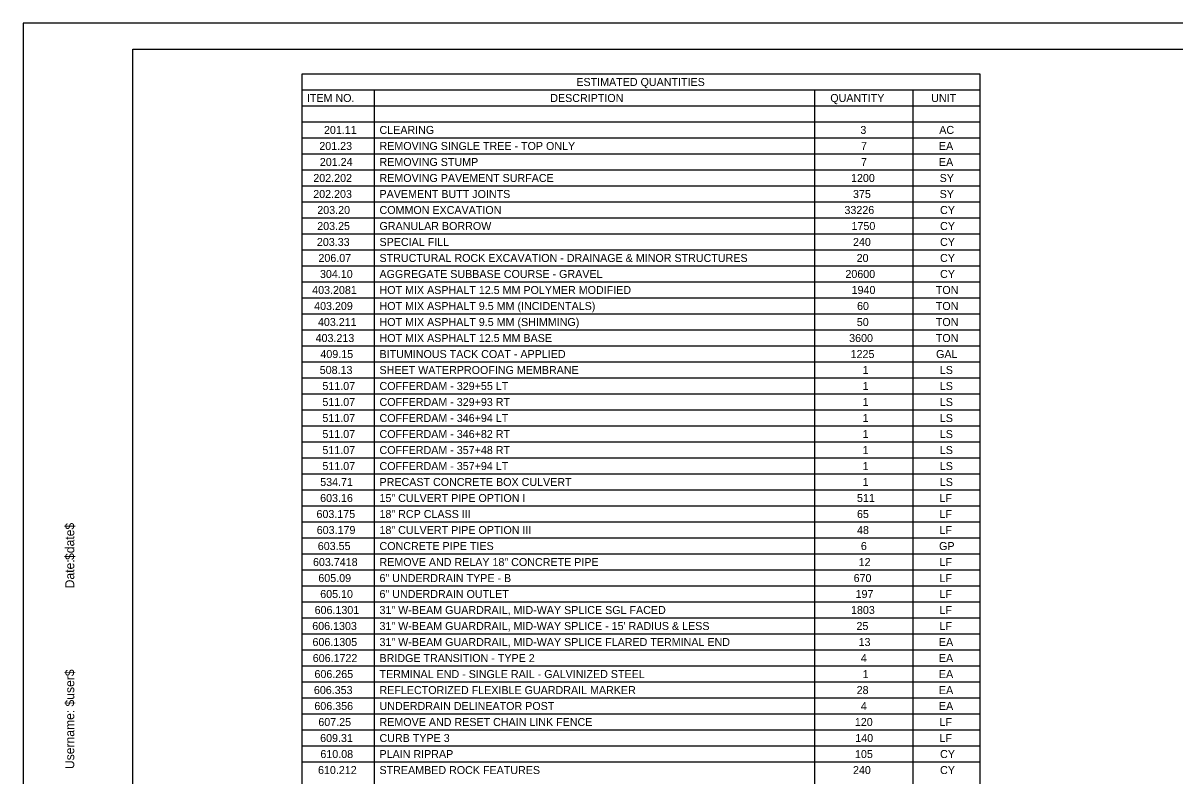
# Model space of a CAD drawing. Extents: x -0.13 to 2.7, y -0.05 to 1.78.
# Drawn here: x -0.135 to 1.282, y 0.856 to 1.782 of the extents above; entities that cross this region are included whole.
import ezdxf

# ---------------------------------------------------------------- set-up
doc = ezdxf.new("R2010")
doc.units = 0
for name, color, linetype in [('ANNOTATION', 7, 'Continuous'), ('BORDER', 7, 'Continuous'), ('Default', 7, 'Continuous'), ('PLOT BOUNDARY', 7, 'Continuous')]:
    doc.layers.add(name, color=color, linetype=linetype)

msp = doc.modelspace()

# ---------------------------------------------------------------- linework, layer by layer
at = {"layer": 'BORDER'}
for p, q in [((0.2083, 1.7003), (1.0417, 1.7003)), ((0.2969, 1.7003), (0.2969, 0.0465)), ((0.8383, 1.7003), (0.8383, 0.0465)), ((0.9596, 1.7003), (0.9596, 0.0465)), ((0.2083, 1.6806), (1.0417, 1.6806)), ((0.2083, 1.6609), (1.0417, 1.6609)), ((0.2083, 1.6413), (1.0417, 1.6413)), ((0.2083, 1.6216), (1.0417, 1.6216)), ((0.2083, 1.6019), (1.0417, 1.6019)), ((0.2083, 1.5822), (1.0417, 1.5822)), ((0.2083, 1.5625), (1.0417, 1.5625)), ((0.2083, 1.5428), (1.0417, 1.5428)), ((0.2083, 1.5231), (1.0417, 1.5231)), ((0.2083, 1.5035), (1.0417, 1.5035)), ((0.2083, 1.4838), (1.0417, 1.4838)), ((0.2083, 1.4641), (1.0417, 1.4641)), ((0.2083, 1.4444), (1.0417, 1.4444)), ((0.2083, 1.4247), (1.0417, 1.4247)), ((0.2083, 1.405), (1.0417, 1.405)), ((0.2083, 1.3853), (1.0417, 1.3853)), ((0.2083, 1.3657), (1.0417, 1.3657)), ((0.2083, 1.346), (1.0417, 1.346)), ((0.2083, 1.3263), (1.0417, 1.3263)), ((0.2083, 1.3066), (1.0417, 1.3066)), ((0.2083, 1.2869), (1.0417, 1.2869)), ((0.2083, 1.2672), (1.0417, 1.2672)), ((0.2083, 1.2475), (1.0417, 1.2475)), ((0.2083, 1.2279), (1.0417, 1.2279)), ((0.2083, 1.2082), (1.0417, 1.2082)), ((0.2083, 1.1885), (1.0417, 1.1885)), ((0.2083, 1.1688), (1.0417, 1.1688)), ((0.2083, 1.1491), (1.0417, 1.1491)), ((0.2083, 1.1294), (1.0417, 1.1294)), ((0.2083, 1.1097), (1.0417, 1.1097)), ((0.2083, 1.09), (1.0417, 1.09)), ((0.2083, 1.0704), (1.0417, 1.0704)), ((0.2083, 1.0507), (1.0417, 1.0507)), ((0.2083, 1.031), (1.0417, 1.031)), ((0.2083, 1.0113), (1.0417, 1.0113)), ((0.2083, 0.9916), (1.0417, 0.9916)), ((0.2083, 0.9719), (1.0417, 0.9719)), ((0.2083, 0.9522), (1.0417, 0.9522)), ((0.2083, 0.9326), (1.0417, 0.9326)), ((0.2083, 0.9129), (1.0417, 0.9129)), ((0.2083, 0.8932), (1.0417, 0.8932)), ((0.2083, 0.8735), (1.0417, 0.8735))]:
    msp.add_line(p, q, dxfattribs=at)
for points in [[(0, 1.75), (2.6667, 1.75), (2.6667, 0), (0, 0)], [(0.2083, 1.72), (1.0417, 1.72), (1.0417, 0.0465), (0.2083, 0.0465)]]:
    msp.add_lwpolyline(points, close=True, dxfattribs=at)
at = {"layer": 'Default'}
for p, q in [((0, 1.75), (1.25, 1.75)), ((1.25, 1.75), (2.5, 1.75))]:
    msp.add_line(p, q, dxfattribs=at)
at = {"layer": 'PLOT BOUNDARY'}
msp.add_lwpolyline([(-0.1349, -0.051), (2.6984, -0.051), (2.6984, 1.7823), (-0.1349, 1.7823)], close=True, dxfattribs=at)

# ---------------------------------------------------------------- texts
at = {"layer": 'ANNOTATION'}
for s, height, p in [('201.11', 0.00984, (0.2352, 1.6459)), ('CLEARING', 0.00984, (0.3035, 1.6459)), ('3', 0.00984, (0.8949, 1.6459)), ('AC', 0.00984, (0.9919, 1.6459)), ('201.23', 0.00984, (0.2295, 1.6262)), ('REMOVING SINGLE TREE - TOP ONLY', 0.009843, (0.3035, 1.6262)), ('7', 0.00984, (0.8957, 1.6262)), ('EA', 0.00984, (0.9915, 1.6262)), ('201.24', 0.00984, (0.2301, 1.6065)), ('REMOVING STUMP', 0.009843, (0.3035, 1.6065)), ('7', 0.00984, (0.8957, 1.6065)), ('EA', 0.00984, (0.9915, 1.6065)), ('202.202', 0.00984, (0.2221, 1.5868)), ('REMOVING PAVEMENT SURFACE', 0.009843, (0.3035, 1.5868)), ('1200', 0.00984, (0.8834, 1.5868)), ('SY', 0.00984, (0.9924, 1.5868)), ('202.203', 0.00984, (0.222, 1.5671)), ('PAVEMENT BUTT JOINTS', 0.009843, (0.3035, 1.5671)), ('375', 0.00984, (0.8858, 1.5671)), ('SY', 0.00984, (0.9924, 1.5671)), ('203.20', 0.00984, (0.227, 1.5474)), ('COMMON EXCAVATION', 0.009843, (0.3035, 1.5474)), ('33226', 0.00984, (0.8753, 1.5474)), ('CY', 0.00984, (0.9929, 1.5474)), ('203.25', 0.00984, (0.2269, 1.5277)), ('GRANULAR BORROW', 0.009843, (0.3035, 1.5277)), ('1750', 0.00984, (0.884, 1.5277)), ('CY', 0.00984, (0.9929, 1.5277)), ('203.33', 0.00984, (0.2265, 1.5081)), ('SPECIAL FILL', 0.009843, (0.3035, 1.5081)), ('240', 0.00984, (0.8858, 1.5081)), ('CY', 0.00984, (0.9929, 1.5081)), ('206.07', 0.00984, (0.2284, 1.4884)), ('STRUCTURAL ROCK EXCAVATION - DRAINAGE & MINOR STRUCTURES', 0.009843, (0.3035, 1.4884)), ('20', 0.00984, (0.8903, 1.4884)), ('CY', 0.00984, (0.9929, 1.4884)), ('304.10', 0.00984, (0.2303, 1.4687)), ('AGGREGATE SUBBASE COURSE - GRAVEL', 0.009843, (0.3035, 1.4687)), ('20600', 0.00984, (0.8765, 1.4687)), ('CY', 0.00984, (0.9929, 1.4687)), ('403.2081', 0.00984, (0.2207, 1.449)), ('HOT MIX ASPHALT 12.5 MM POLYMER MODIFIED', 0.009843, (0.3035, 1.449)), ('1940', 0.00984, (0.8841, 1.449)), ('TON', 0.00984, (0.9877, 1.449)), ('403.209', 0.00984, (0.2231, 1.4293)), ('HOT MIX ASPHALT 9.5 MM (INCIDENTALS)', 0.009843, (0.3035, 1.4293)), ('60', 0.00984, (0.8908, 1.4293)), ('TON', 0.00984, (0.9877, 1.4293)), ('403.211', 0.00984, (0.2278, 1.4096)), ('HOT MIX ASPHALT 9.5 MM (SHIMMING)', 0.009843, (0.3035, 1.4096)), ('50', 0.00984, (0.8905, 1.4096)), ('TON', 0.00984, (0.9877, 1.4096)), ('403.213', 0.00984, (0.2249, 1.3899)), ('HOT MIX ASPHALT 12.5 MM BASE', 0.009843, (0.3035, 1.3899)), ('3600', 0.00984, (0.8811, 1.3899)), ('TON', 0.00984, (0.9877, 1.3899)), ('409.15', 0.00984, (0.2308, 1.3702)), ('BITUMINOUS TACK COAT - APPLIED', 0.009843, (0.3035, 1.3702)), ('1225', 0.00984, (0.8829, 1.3702)), ('GAL', 0.00984, (0.988, 1.3702)), ('508.13', 0.00984, (0.23, 1.3506)), ('SHEET WATERPROOFING MEMBRANE', 0.009843, (0.3035, 1.3506)), ('1', 0.00984, (0.8977, 1.3506)), ('LS', 0.00984, (0.9926, 1.3506)), ('511.07', 0.00984, (0.2333, 1.3309)), ('COFFERDAM - 329+55 LT', 0.009843, (0.3035, 1.3309)), ('1', 0.00984, (0.8977, 1.3309)), ('LS', 0.00984, (0.9926, 1.3309)), ('511.07', 0.00984, (0.2333, 1.3112)), ('COFFERDAM - 329+93 RT', 0.009843, (0.3035, 1.3112)), ('1', 0.00984, (0.8977, 1.3112)), ('LS', 0.00984, (0.9926, 1.3112)), ('511.07', 0.00984, (0.2333, 1.2915)), ('COFFERDAM - 346+94 LT', 0.009843, (0.3035, 1.2915)), ('1', 0.00984, (0.8977, 1.2915)), ('LS', 0.00984, (0.9926, 1.2915)), ('511.07', 0.00984, (0.2333, 1.2718)), ('COFFERDAM - 346+82 RT', 0.009843, (0.3035, 1.2718)), ('1', 0.00984, (0.8977, 1.2718)), ('LS', 0.00984, (0.9926, 1.2718)), ('511.07', 0.00984, (0.2333, 1.2521)), ('COFFERDAM - 357+48 RT', 0.009843, (0.3035, 1.2521)), ('1', 0.00984, (0.8977, 1.2521)), ('LS', 0.00984, (0.9926, 1.2521)), ('511.07', 0.00984, (0.2333, 1.2324)), ('COFFERDAM - 357+94 LT', 0.009843, (0.3035, 1.2324)), ('1', 0.00984, (0.8977, 1.2324)), ('LS', 0.00984, (0.9926, 1.2324)), ('534.71', 0.00984, (0.2306, 1.2128)), ('PRECAST CONCRETE BOX CULVERT', 0.009843, (0.3035, 1.2128)), ('1', 0.00984, (0.8977, 1.2128)), ('LS', 0.00984, (0.9926, 1.2128)), ('603.16', 0.00984, (0.2305, 1.1931)), ('15" CULVERT PIPE OPTION I', 0.009843, (0.3035, 1.1931)), ('511', 0.00984, (0.8907, 1.1931)), ('LF', 0.00984, (0.9922, 1.1931)), ('603.175', 0.00984, (0.226, 1.1734)), ('18" RCP CLASS III', 0.009843, (0.3035, 1.1734)), ('65', 0.00984, (0.8907, 1.1734)), ('LF', 0.00984, (0.9922, 1.1734)), ('603.179', 0.00984, (0.2263, 1.1537)), ('18" CULVERT PIPE OPTION III', 0.009843, (0.3035, 1.1537)), ('48', 0.00984, (0.8908, 1.1537)), ('LF', 0.00984, (0.9922, 1.1537)), ('603.55', 0.00984, (0.2276, 1.134)), ('CONCRETE PIPE TIES', 0.009843, (0.3035, 1.134)), ('6', 0.00984, (0.8955, 1.134)), ('GP', 0.00984, (0.9917, 1.134)), ('603.7418', 0.00984, (0.2217, 1.1143)), ('REMOVE AND RELAY 18" CONCRETE PIPE', 0.009843, (0.3035, 1.1143)), ('12', 0.00984, (0.8928, 1.1143)), ('LF', 0.00984, (0.9922, 1.1143)), ('605.09', 0.00984, (0.2283, 1.0946)), ('6" UNDERDRAIN TYPE - B', 0.009843, (0.3035, 1.0946)), ('670', 0.00984, (0.8866, 1.0946)), ('LF', 0.00984, (0.9922, 1.0946)), ('605.10', 0.00984, (0.2306, 1.075)), ('6" UNDERDRAIN OUTLET', 0.009843, (0.3035, 1.075)), ('197', 0.00984, (0.889, 1.075)), ('LF', 0.00984, (0.9922, 1.075)), ('606.1301', 0.00984, (0.2237, 1.0553)), ('31" W-BEAM GUARDRAIL, MID-WAY SPLICE SGL FACED', 0.009843, (0.3035, 1.0553)), ('1803', 0.00984, (0.8834, 1.0553)), ('LF', 0.00984, (0.9922, 1.0553)), ('606.1303', 0.00984, (0.2208, 1.0356)), ('31" W-BEAM GUARDRAIL, MID-WAY SPLICE - 15\' RADIUS & LESS', 0.009843, (0.3035, 1.0356)), ('25', 0.00984, (0.8901, 1.0356)), ('LF', 0.00984, (0.9922, 1.0356)), ('606.1305', 0.00984, (0.2211, 1.0159)), ('31" W-BEAM GUARDRAIL, MID-WAY SPLICE FLARED TERMINAL END', 0.009843, (0.3035, 1.0159)), ('13', 0.00984, (0.8927, 1.0159)), ('EA', 0.00984, (0.9915, 1.0159)), ('606.1722', 0.00984, (0.2214, 0.9962)), ('BRIDGE TRANSITION - TYPE 2', 0.009843, (0.3035, 0.9962)), ('4', 0.00984, (0.8955, 0.9962)), ('EA', 0.00984, (0.9915, 0.9962)), ('606.265', 0.00984, (0.2235, 0.9765)), ('TERMINAL END - SINGLE RAIL - GALVINIZED STEEL', 0.009843, (0.3035, 0.9765)), ('1', 0.00984, (0.8977, 0.9765)), ('EA', 0.00984, (0.9915, 0.9765)), ('606.353', 0.00984, (0.2228, 0.9568)), ('REFLECTORIZED FLEXIBLE GUARDRAIL MARKER', 0.009843, (0.3035, 0.9568)), ('28', 0.00984, (0.8903, 0.9568)), ('EA', 0.00984, (0.9915, 0.9568)), ('606.356', 0.00984, (0.2234, 0.9372)), ('UNDERDRAIN DELINEATOR POST', 0.009843, (0.3035, 0.9372)), ('4', 0.00984, (0.8955, 0.9372)), ('EA', 0.00984, (0.9915, 0.9372)), ('607.25', 0.00984, (0.2283, 0.9175)), ('REMOVE AND RESET CHAIN LINK FENCE', 0.009843, (0.3035, 0.9175)), ('120', 0.00984, (0.8881, 0.9175)), ('LF', 0.00984, (0.9922, 0.9175)), ('609.31', 0.00984, (0.2305, 0.8978)), ('CURB TYPE 3', 0.009843, (0.3035, 0.8978)), ('140', 0.00984, (0.8886, 0.8978)), ('LF', 0.00984, (0.9922, 0.8978)), ('610.08', 0.00984, (0.2308, 0.8781)), ('PLAIN RIPRAP', 0.009843, (0.3035, 0.8781)), ('105', 0.00984, (0.8883, 0.8781)), ('CY', 0.00984, (0.9929, 0.8781)), ('610.212', 0.00984, (0.2279, 0.8584)), ('STREAMBED ROCK FEATURES', 0.009843, (0.3035, 0.8584)), ('240', 0.00984, (0.8858, 0.8584)), ('CY', 0.00984, (0.9929, 0.8584))]:
    msp.add_text(s, height=height, dxfattribs=at).set_placement(p)
at = {"layer": 'BORDER'}
for s, height, p in [('ESTIMATED QUANTITIES', 0.009843, (0.5456, 1.7049)), ('ITEM NO.', 0.00984, (0.2142, 1.6852)), ('DESCRIPTION', 0.009843, (0.5135, 1.6852)), ('QUANTITY', 0.00984, (0.8579, 1.6852)), ('UNIT', 0.00984, (0.982, 1.6852))]:
    msp.add_text(s, height=height, dxfattribs=at).set_placement(p)
for s, p in [('$date$', (-0.0719, 1.1218)), ('Date:', (-0.0719, 1.0869)), ('$user$', (-0.0719, 0.9415)), ('Username:', (-0.0719, 0.8645))]:
    msp.add_text(s, height=0.01116, rotation=90, dxfattribs=at).set_placement(p)

doc.saveas('drawing.dxf')
